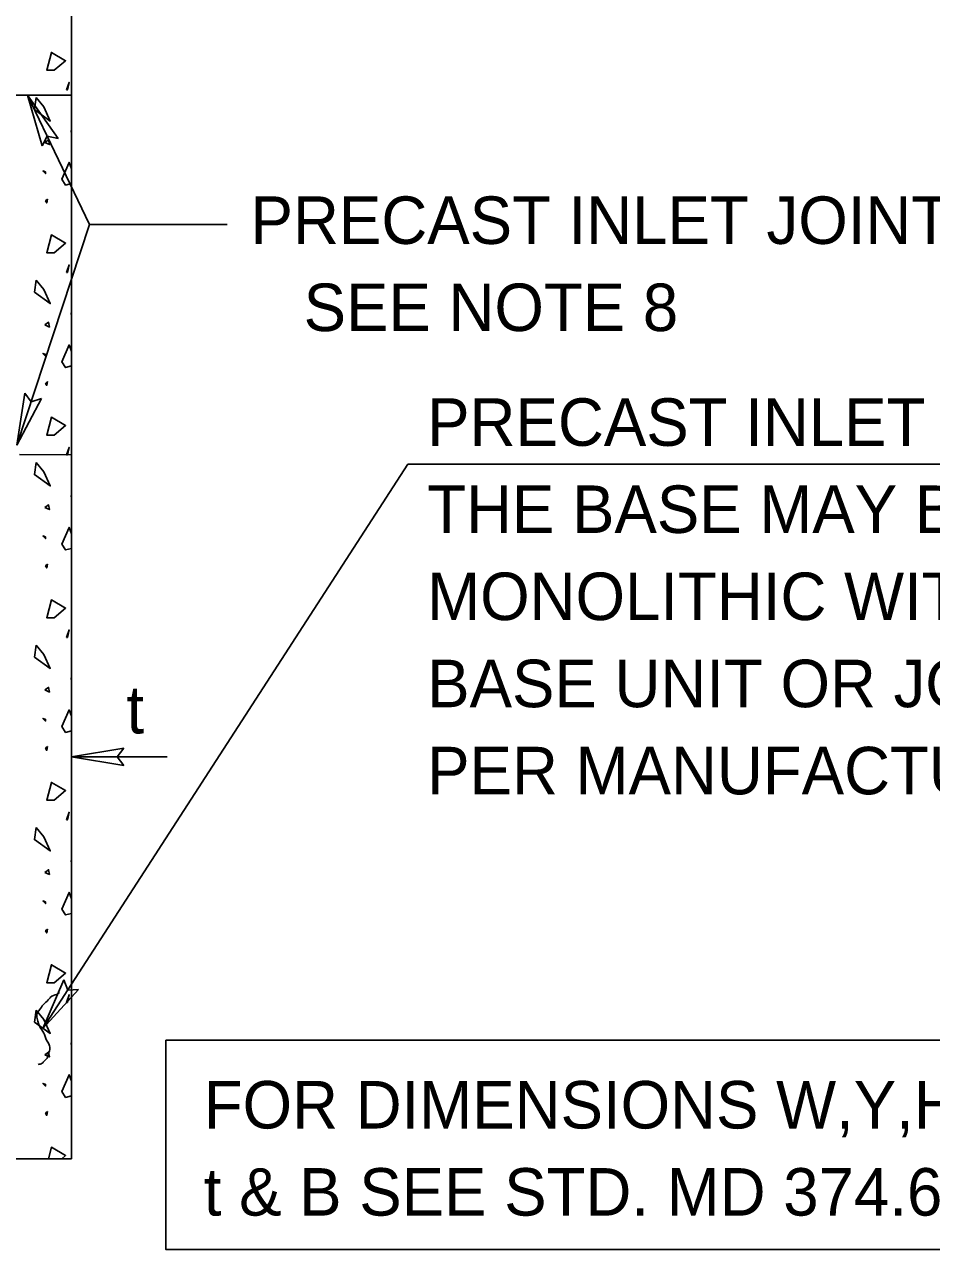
# Model space of a CAD drawing. Extents: x 5.8 to 18, y -5.2 to 5.4.
# Drawn here: x 8.006 to 9.15, y -2.246 to -0.7 of the extents above; entities that cross this region are included whole.
import ezdxf

# ---------------------------------------------------------------- set-up
doc = ezdxf.new("R2010")
doc.units = 0
for name, color, linetype in [('DETL-DIMS', 7, 'Continuous'), ('DETL-LINE', 7, 'Continuous'), ('DETL-NOTE', 7, 'Continuous'), ('DETL-PATT', 7, 'Continuous')]:
    doc.layers.add(name, color=color, linetype=linetype)

msp = doc.modelspace()

# ---------------------------------------------------------------- linework, layer by layer
at = {"layer": 'DETL-DIMS'}
for p, q in [((8.0281, -0.8531), (8.0096, -0.7889)), ((8.0479, -0.8437), (8.0096, -0.7889)), ((8.0876, -0.9522), (8.0096, -0.7889)), ((8.0281, -0.8531), (8.0344, -0.8409)), ((8.0479, -0.8437), (8.0344, -0.8409)), ((8.0876, -0.9522), (7.9959, -1.231)), ((8.0876, -0.9522), (8.2615, -0.9522)), ((8.0061, -1.165), (7.9959, -1.231)), ((8.0269, -1.1718), (7.9959, -1.231)), ((8.0061, -1.165), (8.0139, -1.1763)), ((8.0269, -1.1718), (8.0139, -1.1763)), ((8.4893, -1.255), (8.0288, -1.9673)), ((9.7568, -1.255), (8.4893, -1.255)), ((8.131, -1.6132), (8.0651, -1.6242)), ((8.131, -1.6132), (8.1227, -1.6242)), ((8.0651, -1.6242), (8.1857, -1.6242)), ((8.131, -1.6352), (8.0651, -1.6242)), ((8.131, -1.6352), (8.1227, -1.6242)), ((8.0554, -1.9061), (8.0288, -1.9673)), ((8.0554, -1.9061), (8.0601, -1.9189)), ((8.0738, -1.918), (8.0288, -1.9673)), ((8.0738, -1.918), (8.0601, -1.9189))]:
    msp.add_line(p, q, dxfattribs=at)
msp.add_spline([(8.023, -2.0127), (8.0277, -2.0112), (8.0309, -2.008), (8.034, -2.0049), (8.0356, -2.0002), (8.0371, -1.9955), (8.0371, -1.9892), (8.0324, -1.9798), (8.0309, -1.9751), (8.0262, -1.9672), (8.0215, -1.9547), (8.0215, -1.9484), (8.0246, -1.9437), (8.0293, -1.9374), (8.0356, -1.9311), (8.0403, -1.9264), (8.0481, -1.9233), (8.0497, -1.9217)], degree=3, dxfattribs=at)
at = {"layer": 'DETL-LINE'}
for p, q in [((8.0651, -2.1318), (8.0651, -0.6101)), ((7.9853, -0.7889), (8.0651, -0.7889)), ((7.9991, -1.2426), (8.0658, -1.2429)), ((6.8791, -2.1318), (8.0651, -2.1318))]:
    msp.add_line(p, q, dxfattribs=at)
at = {"layer": 'DETL-NOTE'}
msp.add_lwpolyline([(8.184, -1.9819), (9.9115, -1.9819), (9.9115, -2.2464), (8.184, -2.2464)], close=True, dxfattribs=at)
at = {"layer": 'DETL-PATT'}
for points in [[(8.043, -0.7575), (8.0574, -0.7454), (8.0396, -0.7349), (8.0337, -0.7575)], [(8.0585, -0.7824), (8.0597, -0.7824), (8.0619, -0.7728)], [(8.0204, -0.792), (8.0182, -0.8072), (8.0382, -0.8216), (8.03, -0.8038)], [(8.0312, -0.8487), (8.0371, -0.8513), (8.036, -0.8453)], [(8.0323, -0.8857), (8.0289, -0.8846), (8.0323, -0.888)], [(8.0348, -0.9202), (8.0323, -0.9224), (8.0337, -0.925)], [(8.043, -0.9879), (8.0574, -0.9758), (8.0396, -0.9653), (8.0337, -0.9879)], [(8.0585, -1.0128), (8.0597, -1.0128), (8.0619, -1.0032)], [(8.0204, -1.0224), (8.0182, -1.0376), (8.0382, -1.052), (8.03, -1.0342)], [(8.0312, -1.0791), (8.0371, -1.0817), (8.036, -1.0757)], [(8.0323, -1.1161), (8.0289, -1.115), (8.0323, -1.1184)], [(8.0348, -1.1506), (8.0323, -1.1528), (8.0337, -1.1554)], [(8.043, -1.2183), (8.0574, -1.2062), (8.0396, -1.1957), (8.0337, -1.2183)], [(8.0585, -1.2432), (8.0597, -1.2432), (8.0619, -1.2336)], [(8.0204, -1.2528), (8.0182, -1.268), (8.0382, -1.2824), (8.03, -1.2646)], [(8.0312, -1.3095), (8.0371, -1.3121), (8.036, -1.3062)], [(8.0323, -1.3465), (8.0289, -1.3454), (8.0323, -1.3488)], [(8.0348, -1.381), (8.0323, -1.3832), (8.0337, -1.3858)], [(8.043, -1.4487), (8.0574, -1.4366), (8.0396, -1.4262), (8.0337, -1.4487)], [(8.0585, -1.4736), (8.0597, -1.4736), (8.0619, -1.464)], [(8.0204, -1.4832), (8.0182, -1.4984), (8.0382, -1.5128), (8.03, -1.495)], [(8.0312, -1.5399), (8.0371, -1.5425), (8.036, -1.5366)], [(8.0323, -1.5769), (8.0289, -1.5758), (8.0323, -1.5792)], [(8.0348, -1.6114), (8.0323, -1.6136), (8.0337, -1.6162)], [(8.043, -1.6791), (8.0574, -1.667), (8.0396, -1.6566), (8.0337, -1.6791)], [(8.0585, -1.704), (8.0597, -1.704), (8.0619, -1.6944)], [(8.0204, -1.7136), (8.0182, -1.7288), (8.0382, -1.7432), (8.03, -1.7255)], [(8.0312, -1.7703), (8.0371, -1.7729), (8.036, -1.7669)], [(8.0323, -1.8073), (8.0289, -1.8062), (8.0323, -1.8096)], [(8.0348, -1.8418), (8.0323, -1.844), (8.0337, -1.8466)], [(8.043, -1.9095), (8.0574, -1.8974), (8.0396, -1.8869), (8.0337, -1.9095)], [(8.0585, -1.9344), (8.0597, -1.9344), (8.0619, -1.9248)], [(8.0204, -1.944), (8.0182, -1.9592), (8.0382, -1.9736), (8.03, -1.9558)], [(8.0312, -2.0007), (8.0371, -2.0033), (8.036, -1.9973)], [(8.0323, -2.0377), (8.0289, -2.0366), (8.0323, -2.04)], [(8.0348, -2.0722), (8.0323, -2.0744), (8.0337, -2.077)]]:
    msp.add_lwpolyline(points, close=True, dxfattribs=at)
for points in [[(8.0651, -0.8337), (8.0645, -0.8335), (8.0651, -0.838)], [(8.0651, -0.882), (8.0619, -0.8738), (8.0526, -0.895), (8.0574, -0.9024), (8.0651, -0.9004)], [(8.0651, -1.064), (8.0645, -1.0639), (8.0651, -1.0684)], [(8.0651, -1.1124), (8.0619, -1.1043), (8.0526, -1.1255), (8.0574, -1.1328), (8.0651, -1.1308)], [(8.0651, -1.2945), (8.0645, -1.2943), (8.0651, -1.2987)], [(8.0651, -1.3428), (8.0619, -1.3347), (8.0526, -1.3558), (8.0574, -1.3632), (8.0651, -1.3612)], [(8.0651, -1.5249), (8.0645, -1.5247), (8.0651, -1.5291)], [(8.0651, -1.5732), (8.0619, -1.5651), (8.0526, -1.5862), (8.0574, -1.5936), (8.0651, -1.5916)], [(8.0651, -1.7553), (8.0645, -1.7551), (8.0651, -1.7595)], [(8.0651, -1.8037), (8.0619, -1.7955), (8.0526, -1.8166), (8.0574, -1.824), (8.0651, -1.822)], [(8.0651, -1.9857), (8.0645, -1.9855), (8.0651, -1.99)], [(8.0651, -2.034), (8.0619, -2.0258), (8.0526, -2.047), (8.0574, -2.0544), (8.0651, -2.0524)], [(8.0527, -2.1318), (8.0574, -2.1278), (8.0396, -2.1173), (8.0358, -2.1318)]]:
    msp.add_lwpolyline(points, dxfattribs=at)

# ---------------------------------------------------------------- texts
at = {"layer": 'DETL-NOTE'}
for s, p in [('PRECAST INLET JOINTS', (8.2909, -0.9768)), ('   SEE NOTE 8', (8.2909, -1.0868)), ('PRECAST INLET BASE-', (8.5137, -1.2317)), ('THE BASE MAY BE CAST', (8.5137, -1.3417)), ('MONOLITHIC WITH THE', (8.5137, -1.4517)), ('BASE UNIT OR JOINTED', (8.5137, -1.5617)), ('t', (8.1343, -1.5948)), ("PER MANUFACTURER'S DESIGN", (8.5137, -1.6717)), ('FOR DIMENSIONS W,Y,H ,H , T ', (8.2318, -2.0936)), ('t & B SEE STD. MD 374.61-01', (8.2318, -2.2036))]:
    msp.add_text(s, height=0.06, dxfattribs=at).set_placement(p)

doc.saveas('drawing.dxf')
